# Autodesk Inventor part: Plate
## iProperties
Shininess: 77.0
Length Units: 11269
Angle Units: 11279
Time Units: 11290
Mass Units: 11283
Length Display Precision: 3
Angle Display Precision: 2
Created: 2002-01
Part Number: Plate
Document SubType Name: Modeling
Designer: ***
Density: 0.0
Volumn: 0.0
Area: 0.0
PropertySet Name: Model Information
Control State: 0
Master: False
Checked Out: False
Author: ***
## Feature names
1. Extrusion1
